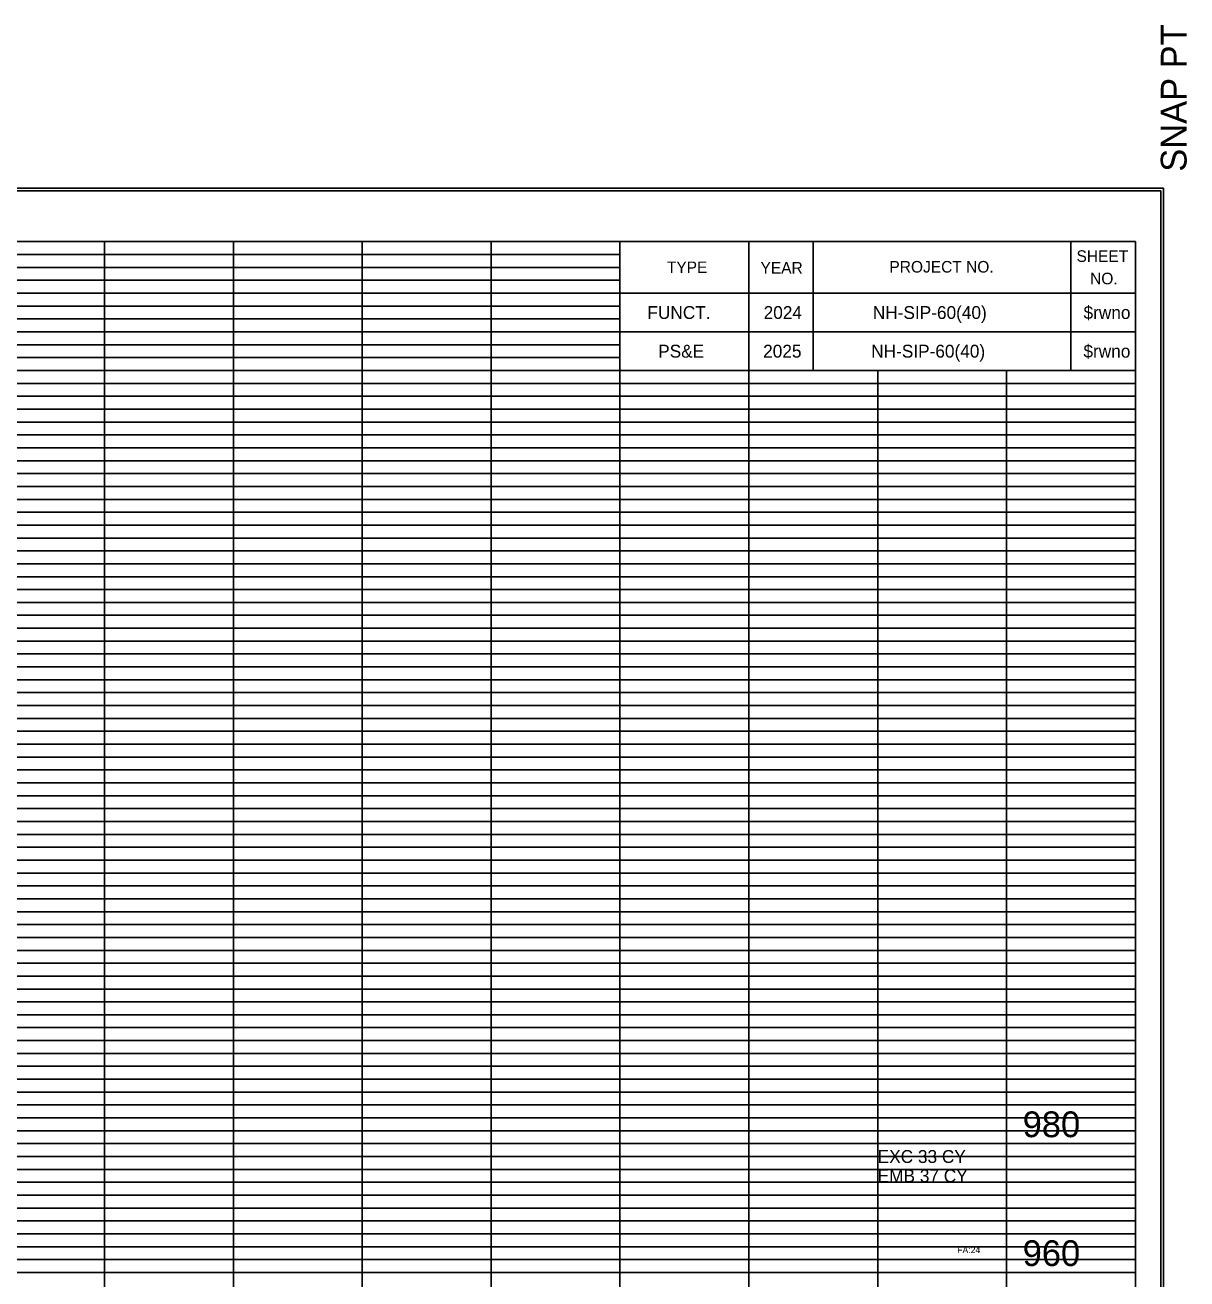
# Model space of a CAD drawing. Extents: x 2313580 to 2322968, y 282099 to 303247.
# Drawn here: x 2318140.1 to 2318320.5, y 287846.7 to 288041.3 of the extents above; entities that cross this region are included whole.
import ezdxf

# ---------------------------------------------------------------- set-up
doc = ezdxf.new("R2010")
doc.units = 0
for name, color, linetype in [('DESIGN - EARTHWORK - Excavation Limit Lines', 7, 'Continuous'), ('DESIGN - SCRATCH - User 1', 7, 'Continuous'), ('DESIGN - SHEET - Corner Text', 7, 'Continuous'), ('DESIGN - SHEET - Light Grid', 7, 'Continuous'), ('DESIGN - SHEET - Linework', 7, 'Continuous'), ('DESIGN - SHEET - Plot Shape', 7, 'Continuous'), ('DESIGN - TYPICAL - Text', 7, 'Continuous'), ('Prop_ CL text', 7, 'Continuous')]:
    doc.layers.add(name, color=color, linetype=linetype)

msp = doc.modelspace()

# ---------------------------------------------------------------- linework, layer by layer
at = {"layer": 'DESIGN - SCRATCH - User 1'}
for p, q in [((2318242.48, 287996.67), (2318242.48, 287996.67)), ((2318257.28, 287996.67), (2318257.28, 287996.67)), ((2318282.28, 287996.67), (2318282.28, 287996.67)), ((2318307.28, 287996.67), (2318307.28, 287996.67)), ((2318242.48, 287990.67), (2318242.48, 287990.67)), ((2318257.28, 287990.67), (2318257.28, 287990.67)), ((2318282.28, 287990.67), (2318282.28, 287990.67)), ((2318307.28, 287990.67), (2318307.28, 287990.67))]:
    msp.add_line(p, q, dxfattribs=at)
at = {"layer": 'DESIGN - SHEET - Light Grid'}
for p, q in [((2317992.48, 288005.67), (2318152.48, 288005.67)), ((2318152.48, 288005.67), (2318232.48, 288005.67)), ((2317992.48, 288003.67), (2318152.48, 288003.67)), ((2318152.48, 288003.67), (2318232.48, 288003.67)), ((2317992.48, 288001.67), (2318152.48, 288001.67)), ((2318152.48, 288001.67), (2318232.48, 288001.67)), ((2317992.48, 287999.67), (2318152.48, 287999.67)), ((2318152.48, 287999.67), (2318232.48, 287999.67)), ((2317992.48, 287997.67), (2318152.48, 287997.67)), ((2318152.48, 287997.67), (2318232.48, 287997.67)), ((2317992.48, 287995.67), (2318152.48, 287995.67)), ((2318152.48, 287995.67), (2318232.48, 287995.67)), ((2317992.48, 287993.67), (2318152.48, 287993.67)), ((2318152.48, 287993.67), (2318232.48, 287993.67)), ((2317992.48, 287991.67), (2318152.48, 287991.67)), ((2318152.48, 287991.67), (2318232.48, 287991.67)), ((2317992.48, 287989.67), (2318152.48, 287989.67)), ((2318152.48, 287989.67), (2318232.48, 287989.67)), ((2317992.48, 287985.67), (2318152.48, 287985.67)), ((2318152.48, 287985.67), (2318312.48, 287985.67)), ((2317992.48, 287983.67), (2318152.48, 287983.67)), ((2318152.48, 287983.67), (2318312.48, 287983.67)), ((2317992.48, 287981.67), (2318152.48, 287981.67)), ((2318152.48, 287981.67), (2318312.48, 287981.67)), ((2317992.48, 287979.67), (2318152.48, 287979.67)), ((2318152.48, 287979.67), (2318312.48, 287979.67)), ((2317992.48, 287977.67), (2318152.48, 287977.67)), ((2318152.48, 287977.67), (2318312.48, 287977.67)), ((2317992.48, 287975.67), (2318152.48, 287975.67)), ((2318152.48, 287975.67), (2318312.48, 287975.67)), ((2317992.48, 287973.67), (2318152.48, 287973.67)), ((2318152.48, 287973.67), (2318312.48, 287973.67)), ((2317992.48, 287971.67), (2318152.48, 287971.67)), ((2318152.48, 287971.67), (2318312.48, 287971.67)), ((2317992.48, 287969.67), (2318152.48, 287969.67)), ((2318152.48, 287969.67), (2318312.48, 287969.67)), ((2317992.48, 287965.67), (2318152.48, 287965.67)), ((2318152.48, 287965.67), (2318312.48, 287965.67)), ((2317992.48, 287963.67), (2318152.48, 287963.67)), ((2318152.48, 287963.67), (2318312.48, 287963.67)), ((2317992.48, 287961.67), (2318152.48, 287961.67)), ((2318152.48, 287961.67), (2318312.48, 287961.67)), ((2317992.48, 287959.67), (2318152.48, 287959.67)), ((2318152.48, 287959.67), (2318312.48, 287959.67)), ((2317992.48, 287957.67), (2318152.48, 287957.67)), ((2318152.48, 287957.67), (2318312.48, 287957.67)), ((2317992.48, 287955.67), (2318152.48, 287955.67)), ((2318152.48, 287955.67), (2318312.48, 287955.67)), ((2317992.48, 287953.67), (2318152.48, 287953.67)), ((2318152.48, 287953.67), (2318312.48, 287953.67)), ((2317992.48, 287951.67), (2318152.48, 287951.67)), ((2318152.48, 287951.67), (2318312.48, 287951.67)), ((2317992.48, 287949.67), (2318152.48, 287949.67)), ((2318152.48, 287949.67), (2318312.48, 287949.67)), ((2317992.48, 287945.67), (2318152.48, 287945.67)), ((2318152.48, 287945.67), (2318312.48, 287945.67)), ((2317992.48, 287943.67), (2318152.48, 287943.67)), ((2318152.48, 287943.67), (2318312.48, 287943.67)), ((2317992.48, 287941.67), (2318152.48, 287941.67)), ((2318152.48, 287941.67), (2318312.48, 287941.67)), ((2317992.48, 287939.67), (2318152.48, 287939.67)), ((2318152.48, 287939.67), (2318312.48, 287939.67)), ((2317992.48, 287937.67), (2318152.48, 287937.67)), ((2318152.48, 287937.67), (2318312.48, 287937.67)), ((2317992.48, 287935.67), (2318152.48, 287935.67)), ((2318152.48, 287935.67), (2318312.48, 287935.67)), ((2317992.48, 287933.67), (2318152.48, 287933.67)), ((2318152.48, 287933.67), (2318312.48, 287933.67)), ((2317992.48, 287931.67), (2318152.48, 287931.67)), ((2318152.48, 287931.67), (2318312.48, 287931.67)), ((2317992.48, 287929.67), (2318152.48, 287929.67)), ((2318152.48, 287929.67), (2318312.48, 287929.67)), ((2317992.48, 287925.67), (2318152.48, 287925.67)), ((2318152.48, 287925.67), (2318312.48, 287925.67)), ((2317992.48, 287923.67), (2318152.48, 287923.67)), ((2318152.48, 287923.67), (2318312.48, 287923.67)), ((2317992.48, 287921.67), (2318152.48, 287921.67)), ((2318152.48, 287921.67), (2318312.48, 287921.67)), ((2317992.48, 287919.67), (2318152.48, 287919.67)), ((2318152.48, 287919.67), (2318312.48, 287919.67)), ((2317992.48, 287917.67), (2318152.48, 287917.67)), ((2318152.48, 287917.67), (2318312.48, 287917.67)), ((2317992.48, 287915.67), (2318152.48, 287915.67)), ((2318152.48, 287915.67), (2318312.48, 287915.67)), ((2317992.48, 287913.67), (2318152.48, 287913.67)), ((2318152.48, 287913.67), (2318312.48, 287913.67)), ((2317992.48, 287911.67), (2318152.48, 287911.67)), ((2318152.48, 287911.67), (2318312.48, 287911.67)), ((2317992.48, 287909.67), (2318152.48, 287909.67)), ((2318152.48, 287909.67), (2318312.48, 287909.67)), ((2317992.48, 287905.67), (2318152.48, 287905.67)), ((2318152.48, 287905.67), (2318312.48, 287905.67)), ((2317992.48, 287903.67), (2318152.48, 287903.67)), ((2318152.48, 287903.67), (2318312.48, 287903.67)), ((2317992.48, 287901.67), (2318152.48, 287901.67)), ((2318152.48, 287901.67), (2318312.48, 287901.67)), ((2317992.48, 287899.67), (2318152.48, 287899.67)), ((2318152.48, 287899.67), (2318312.48, 287899.67)), ((2317992.48, 287897.67), (2318152.48, 287897.67)), ((2318152.48, 287897.67), (2318312.48, 287897.67)), ((2317992.48, 287895.67), (2318152.48, 287895.67)), ((2318152.48, 287895.67), (2318312.48, 287895.67)), ((2317992.48, 287893.67), (2318152.48, 287893.67)), ((2318152.48, 287893.67), (2318312.48, 287893.67)), ((2317992.48, 287891.67), (2318152.48, 287891.67)), ((2318152.48, 287891.67), (2318312.48, 287891.67)), ((2317992.48, 287889.67), (2318152.48, 287889.67)), ((2318152.48, 287889.67), (2318312.48, 287889.67)), ((2317992.48, 287885.67), (2318152.48, 287885.67)), ((2318152.48, 287885.67), (2318312.48, 287885.67)), ((2317992.48, 287883.67), (2318152.48, 287883.67)), ((2318152.48, 287883.67), (2318312.48, 287883.67)), ((2317992.48, 287881.67), (2318152.48, 287881.67)), ((2318152.48, 287881.67), (2318312.48, 287881.67)), ((2317992.48, 287879.67), (2318152.48, 287879.67)), ((2318152.48, 287879.67), (2318312.48, 287879.67)), ((2317992.48, 287877.67), (2318152.48, 287877.67)), ((2318152.48, 287877.67), (2318312.48, 287877.67)), ((2317992.48, 287875.67), (2318152.48, 287875.67)), ((2318152.48, 287875.67), (2318312.48, 287875.67)), ((2317992.48, 287873.67), (2318152.48, 287873.67)), ((2318152.48, 287873.67), (2318312.48, 287873.67)), ((2317992.48, 287871.67), (2318152.48, 287871.67)), ((2318152.48, 287871.67), (2318312.48, 287871.67)), ((2317992.48, 287869.67), (2318152.48, 287869.67)), ((2318152.48, 287869.67), (2318312.48, 287869.67)), ((2317992.48, 287865.67), (2318152.48, 287865.67)), ((2318152.48, 287865.67), (2318312.48, 287865.67)), ((2317992.48, 287863.67), (2318152.48, 287863.67)), ((2318152.48, 287863.67), (2318312.48, 287863.67)), ((2317992.48, 287861.67), (2318152.48, 287861.67)), ((2318152.48, 287861.67), (2318312.48, 287861.67)), ((2317992.48, 287859.67), (2318152.48, 287859.67)), ((2318152.48, 287859.67), (2318312.48, 287859.67)), ((2317992.48, 287857.67), (2318152.48, 287857.67)), ((2318152.48, 287857.67), (2318312.48, 287857.67)), ((2317992.48, 287855.67), (2318152.48, 287855.67)), ((2318152.48, 287855.67), (2318312.48, 287855.67)), ((2317992.48, 287853.67), (2318152.48, 287853.67)), ((2318152.48, 287853.67), (2318312.48, 287853.67)), ((2317992.48, 287851.67), (2318152.48, 287851.67)), ((2318152.48, 287851.67), (2318312.48, 287851.67)), ((2317992.48, 287849.67), (2318152.48, 287849.67)), ((2318152.48, 287849.67), (2318312.48, 287849.67))]:
    msp.add_line(p, q, dxfattribs=at)
at = {"layer": 'DESIGN - SHEET - Linework'}
for p, q in [((2317636.02, 288015.95), (2318316.82, 288015.95)), ((2318316.82, 288015.95), (2318316.82, 287579.39)), ((2318152.48, 287587.67), (2318152.48, 288007.67)), ((2318172.48, 287587.67), (2318172.48, 288007.67)), ((2318192.48, 287587.67), (2318192.48, 288007.67)), ((2318212.48, 287587.67), (2318212.48, 288007.67)), ((2317672.48, 287987.67), (2318232.48, 287987.67)), ((2318232.48, 287587.67), (2318232.48, 287987.67)), ((2318252.48, 287587.67), (2318252.48, 287987.67)), ((2318272.48, 287587.67), (2318272.48, 287987.67)), ((2318292.48, 287587.67), (2318292.48, 287987.67)), ((2317672.48, 287967.67), (2318312.48, 287967.67)), ((2317672.48, 287947.67), (2318312.48, 287947.67)), ((2317672.48, 287927.67), (2318312.48, 287927.67)), ((2317672.48, 287907.67), (2318312.48, 287907.67)), ((2317672.48, 287887.67), (2318312.48, 287887.67)), ((2317672.48, 287867.67), (2318312.48, 287867.67)), ((2317672.48, 287847.67), (2318312.48, 287847.67))]:
    msp.add_line(p, q, dxfattribs=at)
for points in [[(2317672.48, 288007.67), (2317672.48, 287587.67), (2318312.48, 287587.67), (2318312.48, 288007.67), (2317672.48, 288007.67)], [(2318232.48, 288007.67), (2318232.48, 287987.67), (2318312.48, 287987.67), (2318312.48, 288007.67), (2318302.48, 288007.67), (2318302.48, 287987.67), (2318262.48, 287987.67), (2318262.48, 288007.67), (2318252.48, 288007.67), (2318252.48, 287987.67), (2318312.48, 287987.67), (2318232.48, 287987.67), (2318232.48, 287993.67), (2318312.48, 287993.67), (2318312.48, 287999.67), (2318232.48, 287999.67)]]:
    msp.add_lwpolyline(points, dxfattribs=at)
at = {"layer": 'DESIGN - SHEET - Plot Shape'}
for points in [[(2317636.42, 288015.55), (2318316.42, 288015.55), (2318316.42, 287579.79), (2317636.42, 287579.79)], [(2317655.48, 288007.67), (2318312.48, 288007.67), (2318312.48, 287582.67), (2317655.48, 287582.67)]]:
    msp.add_lwpolyline(points, close=True, dxfattribs=at)

# ---------------------------------------------------------------- texts
at = {"layer": 'DESIGN - EARTHWORK - Excavation Limit Lines'}
for s, p in [('EXC 33 CY', (2318272.48, 287864.67)), ('EMB 37 CY', (2318272.48, 287861.67))]:
    msp.add_text(s, height=2, dxfattribs=at).set_placement(p)
at = {"layer": 'DESIGN - SHEET - Corner Text'}
for s, height, rotation, p in [('  SNAP PT', 4, 90, (2318320.42, 288015.55)), ('SHEET', 1.8, 360, (2318303.34, 288004.53)), ('TYPE', 1.8, 360, (2318239.76, 288002.79)), ('YEAR', 1.8, 360, (2318254.29, 288002.71)), ('PROJECT NO.', 1.8, 360, (2318274.3, 288002.87)), ('NO.', 1.8, 360, (2318305.45, 288001.05)), ('  FUNCT.   ', 2, 360, (2318235.25, 287995.67)), ('2024', 2, 360, (2318254.78, 287995.67)), ('$rwno', 2, 360, (2318304.43, 287995.67))]:
    msp.add_text(s, height=height, rotation=rotation, dxfattribs=at).set_placement(p)
for s, p in [('   NH-SIP-60(40)    ', (2318269.49, 287995.67)), (' PS&E ', (2318237.67, 287989.67)), ('2025', (2318254.7, 287989.67)), ('   NH-SIP-60(40)    ', (2318269.24, 287989.67)), ('$rwno', (2318304.41, 287989.67))]:
    msp.add_text(s, height=2, dxfattribs=at).set_placement(p)
at = {"layer": 'DESIGN - TYPICAL - Text'}
for s, p in [('980', (2318294.98, 287868.67)), ('960', (2318294.98, 287848.67))]:
    msp.add_text(s, height=4, dxfattribs=at).set_placement(p)
at = {"layer": 'Prop_ CL text'}
msp.add_text('FA:24', height=1, dxfattribs=at).set_placement((2318284.83, 287850.67))

doc.saveas('drawing.dxf')
